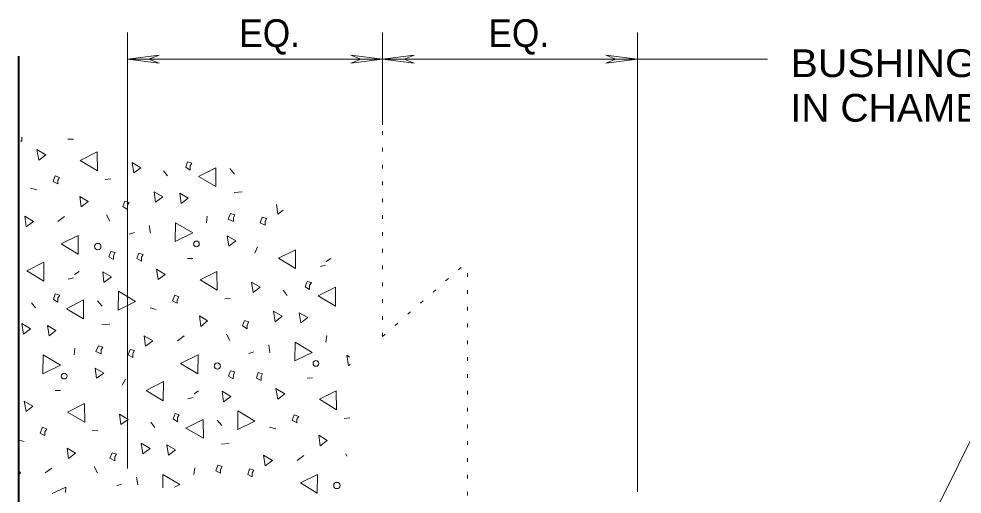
# Model space of a CAD drawing. Extents: x 312583 to 312854, y 144419 to 144597.
# Drawn here: x 312721.51 to 312747.3, y 144558.59 to 144571.59 of the extents above; entities that cross this region are included whole.
import ezdxf

# ---------------------------------------------------------------- set-up
doc = ezdxf.new("R2010")
doc.units = 0
doc.header["$LTSCALE"] = 0.3
doc.linetypes.add('DOTTED', pattern=[1.5, 0.3, -1.2])
doc.layers.add('1', color=7, linetype='Continuous', lineweight=40)
doc.layers.add('2', color=7, linetype='Continuous', lineweight=13)

msp = doc.modelspace()

# ---------------------------------------------------------------- linework, layer by layer
at = {"layer": '1'}
msp.add_line((312721.5141, 144556.6347), (312721.5141, 144570.5727), dxfattribs=at)
at = {"layer": '2'}
for p, q in [((312724.4811, 144559.2873), (312724.4811, 144571.2167)), ((312731.4578, 144568.6943), (312731.4578, 144571.2167)), ((312738.4268, 144558.651), (312738.4268, 144571.2167)), ((312724.4811, 144570.4883), (312725.3474, 144570.5957)), ((312725.3474, 144570.5957), (312725.0714, 144570.4883)), ((312730.5914, 144570.5957), (312730.8674, 144570.4883)), ((312731.4578, 144570.4883), (312730.5914, 144570.5957)), ((312731.4578, 144570.4883), (312732.3241, 144570.5957)), ((312732.3241, 144570.5957), (312732.0481, 144570.4883)), ((312737.5604, 144570.5957), (312737.8364, 144570.4883)), ((312738.4268, 144570.4883), (312737.5604, 144570.5957)), ((312731.4578, 144570.4883), (312724.4811, 144570.4883)), ((312724.4811, 144570.4883), (312725.3474, 144570.381)), ((312725.3474, 144570.381), (312725.0714, 144570.4883)), ((312730.5914, 144570.381), (312730.8674, 144570.4883)), ((312731.4578, 144570.4883), (312730.5914, 144570.381)), ((312731.4578, 144570.4883), (312732.3241, 144570.381)), ((312732.3241, 144570.381), (312732.0481, 144570.4883)), ((312737.5604, 144570.381), (312737.8364, 144570.4883)), ((312738.4268, 144570.4883), (312737.5604, 144570.381)), ((312721.5984, 144568.3417), (312721.6061, 144568.357)), ((312722.8558, 144568.3033), (312723.0091, 144568.3033)), ((312727.2794, 144567.4983), (312727.4098, 144567.345)), ((312723.8754, 144567.1993), (312724.0288, 144567.2147)), ((312725.4701, 144567.437), (312725.5774, 144567.2913)), ((312721.8284, 144566.954), (312722.0048, 144566.9157)), ((312727.4021, 144566.839), (312727.6168, 144566.8543)), ((312728.5598, 144566.5093), (312728.5981, 144566.2487)), ((312723.9138, 144566.2257), (312724.0058, 144566.057)), ((312726.6431, 144566.011), (312726.6661, 144566.195)), ((312728.5981, 144566.2487), (312728.7438, 144566.356)), ((312722.7638, 144566.1797), (312722.5798, 144566.0493)), ((312725.0791, 144565.9343), (312725.1098, 144565.7273)), ((312724.5271, 144565.6967), (312724.6728, 144565.7427)), ((312728.0384, 144565.3517), (312727.9618, 144565.183)), ((312726.1294, 144565.0297), (312726.2751, 144565.0373)), ((312729.9168, 144564.953), (312730.0471, 144565.0297)), ((312723.0321, 144564.6003), (312723.1624, 144564.677)), ((312729.7481, 144564.815), (312729.8938, 144564.8533)), ((312722.8634, 144564.47), (312723.0091, 144564.5083)), ((312728.7438, 144564.1633), (312728.8511, 144564.0253)), ((312723.6684, 144563.8797), (312723.7911, 144563.7263)), ((312727.1414, 144563.9333), (312727.2948, 144563.941)), ((312721.8591, 144563.8183), (312721.9664, 144563.6803)), ((312725.1021, 144563.688), (312725.2708, 144563.642)), ((312723.7834, 144563.2203), (312723.9981, 144563.2357)), ((312726.0374, 144562.9137), (312725.8534, 144562.7833)), ((312727.1874, 144562.9597), (312727.2794, 144562.791)), ((312729.9091, 144562.745), (312729.9321, 144562.929)), ((312723.0244, 144562.4), (312723.0474, 144562.584)), ((312728.3528, 144562.6683), (312728.3758, 144562.4537)), ((312727.8008, 144562.4307), (312727.9388, 144562.4767)), ((312730.5224, 144562.101), (312730.5761, 144562.1393)), ((312724.4274, 144561.733), (312724.3431, 144561.5643)), ((312729.3954, 144561.7637), (312729.5411, 144561.7713)), ((312748.2938, 144561.5873), (312746.0704, 144557.11)), ((312722.5108, 144561.4187), (312722.6564, 144561.4187)), ((312726.3058, 144561.3343), (312726.4284, 144561.411)), ((312726.1371, 144561.1963), (312726.2828, 144561.2347)), ((312725.1251, 144560.5523), (312725.2324, 144560.4067)), ((312726.9344, 144560.6137), (312727.0648, 144560.4603)), ((312730.4074, 144560.6597), (312730.5608, 144560.675)), ((312723.5228, 144560.3147), (312723.6761, 144560.33)), ((312728.3681, 144560.422), (312728.5444, 144560.376)), ((312721.5294, 144560.0617), (312721.6598, 144560.031)), ((312727.0571, 144559.9543), (312727.2641, 144559.9697)), ((312729.3034, 144559.64), (312729.1194, 144559.5097)), ((312730.4534, 144559.686), (312730.4841, 144559.6247)), ((312722.4188, 144559.295), (312722.2348, 144559.1647)), ((312723.5688, 144559.341), (312723.6608, 144559.1723)), ((312726.2981, 144559.1263), (312726.3211, 144559.3103)), ((312724.7341, 144559.0497), (312724.7648, 144558.8427)), ((312725.4471, 144559.1263), (312725.4471, 144558.7583)), ((312724.1821, 144558.812), (312724.3201, 144558.858))]:
    msp.add_line(p, q, dxfattribs=at)
at = {"layer": '2', "linetype": 'DOTTED'}
for p, q in [((312731.4578, 144562.8983), (312731.4578, 144568.6943)), ((312731.4578, 144562.8983), (312733.7808, 144564.9453)), ((312733.7808, 144555.7913), (312733.7808, 144564.9453))]:
    msp.add_line(p, q, dxfattribs=at)
at = {"layer": '2'}
for points in [[(312741.9841, 144570.4883), (312738.4268, 144570.4883), (312731.4578, 144570.4883)], [(312721.5601, 144568.2497), (312721.5984, 144568.2343), (312721.5984, 144568.3417)], [(312730.5531, 144562.331), (312730.4841, 144562.3847), (312730.5224, 144562.101)], [(312721.5218, 144559.134), (312721.5601, 144559.1647), (312721.5294, 144559.1953)], [(312725.7691, 144558.7813), (312725.9148, 144558.8503), (312725.4471, 144559.1263)], [(312722.7868, 144558.628), (312722.7944, 144558.7813), (312722.4264, 144558.605)]]:
    msp.add_lwpolyline(points, dxfattribs=at)
for points in [[(312722.0584, 144567.7283), (312722.2501, 144567.874), (312722.0048, 144568.012)], [(312723.6608, 144567.437), (312723.6531, 144567.9507), (312723.1931, 144567.713)], [(312724.6574, 144567.3757), (312724.8491, 144567.5137), (312724.6114, 144567.6593)], [(312726.1984, 144567.5673), (312726.2444, 144567.644), (312726.1294, 144567.6747), (312726.0758, 144567.529), (312726.1984, 144567.4523)], [(312726.9038, 144567), (312726.8961, 144567.5137), (312726.4284, 144567.276)], [(312722.5798, 144567.1763), (312722.6258, 144567.253), (312722.5108, 144567.299), (312722.4494, 144567.138), (312722.5798, 144567.0767)], [(312723.2161, 144566.448), (312723.4078, 144566.5937), (312723.1778, 144566.7317)], [(312725.2478, 144566.5707), (312725.4471, 144566.724), (312725.2094, 144566.862)], [(312725.9531, 144566.54), (312726.1448, 144566.6857), (312725.9148, 144566.8237)], [(312724.4888, 144566.494), (312724.5271, 144566.563), (312724.4121, 144566.6013), (312724.3584, 144566.4557), (312724.4888, 144566.379)], [(312721.7134, 144565.9037), (312721.9128, 144566.0493), (312721.6751, 144566.195)], [(312727.3791, 144566.149), (312727.4174, 144566.2257), (312727.3024, 144566.264), (312727.2411, 144566.1107), (312727.3791, 144566.0417)], [(312725.7998, 144566.011), (312725.7921, 144565.4973), (312726.2674, 144565.735)], [(312728.2454, 144566.0493), (312728.2838, 144566.126), (312728.1688, 144566.1643), (312728.1151, 144566.011), (312728.2454, 144565.942)], [(312723.1394, 144565.1523), (312723.1394, 144565.666), (312722.6718, 144565.436)], [(312727.2564, 144565.367), (312727.4481, 144565.5127), (312727.2104, 144565.6507)], [(312724.1054, 144565.114), (312724.1514, 144565.1983), (312724.0288, 144565.229), (312723.9751, 144565.0833), (312724.0978, 144565.0067)], [(312724.8644, 144565.068), (312724.9104, 144565.1447), (312724.7954, 144565.183), (312724.7418, 144565.0297), (312724.8644, 144564.9607)], [(312729.0811, 144564.7613), (312729.0811, 144565.275), (312728.6134, 144565.045)], [(312722.1964, 144564.4163), (312722.1964, 144564.93), (312721.7288, 144564.6923)], [(312723.8371, 144564.378), (312724.0441, 144564.5313), (312723.8064, 144564.6693)], [(312725.3244, 144564.4547), (312725.5161, 144564.6003), (312725.2784, 144564.746)], [(312726.9344, 144564.1633), (312726.9268, 144564.677), (312726.4668, 144564.447)], [(312727.9234, 144564.102), (312728.1151, 144564.2477), (312727.8774, 144564.3857)], [(312729.4644, 144564.2937), (312729.5181, 144564.378), (312729.3954, 144564.4087), (312729.3418, 144564.2553), (312729.4644, 144564.1863)], [(312724.2358, 144564.1403), (312724.2281, 144563.619), (312724.7034, 144563.8567)], [(312730.1698, 144563.734), (312730.1698, 144564.2477), (312729.7021, 144564.01)], [(312722.5798, 144563.9487), (312722.6334, 144564.033), (312722.5108, 144564.0637), (312722.4571, 144563.9103), (312722.5798, 144563.8413)], [(312723.2851, 144563.3813), (312723.2851, 144563.9027), (312722.8174, 144563.6573)], [(312725.8458, 144563.9027), (312725.8918, 144563.987), (312725.7768, 144564.033), (312725.7154, 144563.872), (312725.8458, 144563.8107)], [(312726.4898, 144563.1743), (312726.6738, 144563.3277), (312726.4514, 144563.4657)], [(312728.5214, 144563.3047), (312728.7131, 144563.458), (312728.4754, 144563.596)], [(312729.2268, 144563.274), (312729.4108, 144563.4197), (312729.1808, 144563.55)], [(312721.6368, 144562.9597), (312721.8284, 144563.1053), (312721.5908, 144563.251)], [(312722.3421, 144562.9213), (312722.5261, 144563.067), (312722.2961, 144563.205)], [(312727.7548, 144563.2203), (312727.8008, 144563.297), (312727.6858, 144563.3353), (312727.6244, 144563.1897), (312727.7548, 144563.113)], [(312724.9794, 144562.6377), (312725.1788, 144562.7833), (312724.9411, 144562.9213)], [(312723.7604, 144562.5303), (312723.8064, 144562.607), (312723.6914, 144562.6453), (312723.6224, 144562.492), (312723.7604, 144562.423)], [(312729.0658, 144562.745), (312729.0581, 144562.2313), (312729.5334, 144562.4613)], [(312722.1811, 144562.4), (312722.1734, 144561.8787), (312722.6488, 144562.1163)], [(312724.6268, 144562.4383), (312724.6728, 144562.515), (312724.5578, 144562.5457), (312724.5041, 144562.4), (312724.6268, 144562.3233)], [(312726.4054, 144561.8787), (312726.4131, 144562.4), (312725.9378, 144562.1623)], [(312723.6378, 144561.756), (312723.8371, 144561.894), (312723.5994, 144562.032)], [(312727.3791, 144561.848), (312727.4174, 144561.9323), (312727.3024, 144561.963), (312727.2488, 144561.8097), (312727.3714, 144561.7407)], [(312728.1381, 144561.802), (312728.1764, 144561.8787), (312728.0614, 144561.917), (312728.0078, 144561.7637), (312728.1381, 144561.6947)], [(312725.4624, 144561.1427), (312725.4701, 144561.664), (312724.9948, 144561.4263)], [(312727.1108, 144561.112), (312727.3101, 144561.2577), (312727.0724, 144561.4033)], [(312728.5981, 144561.1887), (312728.7821, 144561.3343), (312728.5444, 144561.4723)], [(312730.2004, 144560.8973), (312730.1928, 144561.411), (312729.7328, 144561.181)], [(312721.7134, 144560.8437), (312721.8974, 144560.9893), (312721.6598, 144561.1273)], [(312723.3158, 144560.5523), (312723.3081, 144561.066), (312722.8481, 144560.8283)], [(312724.3048, 144560.491), (312724.5041, 144560.629), (312724.2664, 144560.7747)], [(312725.8534, 144560.6827), (312725.8994, 144560.7593), (312725.7844, 144560.79), (312725.7308, 144560.6443), (312725.8534, 144560.5677)], [(312727.5018, 144560.8667), (312727.5018, 144560.353), (312727.9694, 144560.583)], [(312726.5588, 144560.1153), (312726.5511, 144560.629), (312726.0834, 144560.3913)], [(312729.1118, 144560.6367), (312729.1654, 144560.7133), (312729.0428, 144560.7593), (312728.9891, 144560.606), (312729.1118, 144560.537)], [(312722.2271, 144560.2917), (312722.2808, 144560.3683), (312722.1581, 144560.4143), (312722.0968, 144560.2533), (312722.2271, 144560.192)], [(312729.7558, 144559.9083), (312729.9474, 144560.054), (312729.7174, 144560.1997)], [(312722.8711, 144559.5633), (312723.0628, 144559.709), (312722.8328, 144559.847)], [(312724.9028, 144559.686), (312725.1021, 144559.8393), (312724.8568, 144559.9773)], [(312725.6081, 144559.6553), (312725.7998, 144559.801), (312725.5621, 144559.939)], [(312724.1361, 144559.6093), (312724.1821, 144559.6783), (312724.0671, 144559.7167), (312724.0058, 144559.571), (312724.1361, 144559.4943)], [(312728.2454, 144559.364), (312728.4524, 144559.5097), (312728.2071, 144559.6553)], [(312727.0264, 144559.2643), (312727.0724, 144559.341), (312726.9574, 144559.3793), (312726.8961, 144559.226), (312727.0264, 144559.157)], [(312727.8928, 144559.1647), (312727.9388, 144559.2413), (312727.8238, 144559.2797), (312727.7701, 144559.1263), (312727.8928, 144559.0573)], [(312729.6714, 144558.6127), (312729.6791, 144559.1263), (312729.2114, 144558.8963)]]:
    msp.add_lwpolyline(points, close=True, dxfattribs=at)
for centre, radius in [((312723.6716, 144565.3604), 0.0865), ((312726.3679, 144565.4332), 0.0783), ((312726.9405, 144562.0915), 0.0865), ((312729.6369, 144562.1642), 0.0783), ((312722.752, 144561.8173), 0.0783), ((312730.2095, 144558.8225), 0.0865)]:
    msp.add_circle(centre, radius, dxfattribs=at)

# ---------------------------------------------------------------- texts
for s, width, p in [('EQ.', 0.95, (312727.5392, 144570.8198)), ('EQ.', 0.95, (312734.3496, 144570.8198)), ('BUSHING TO BE CENTERED', 1.1, (312742.6128, 144569.9976)), ('IN CHAMBER', 1.05, (312742.6128, 144568.7776))]:
    msp.add_text(s, height=0.76, dxfattribs=dict(at, width=width)).set_placement(p)

doc.saveas('drawing.dxf')
